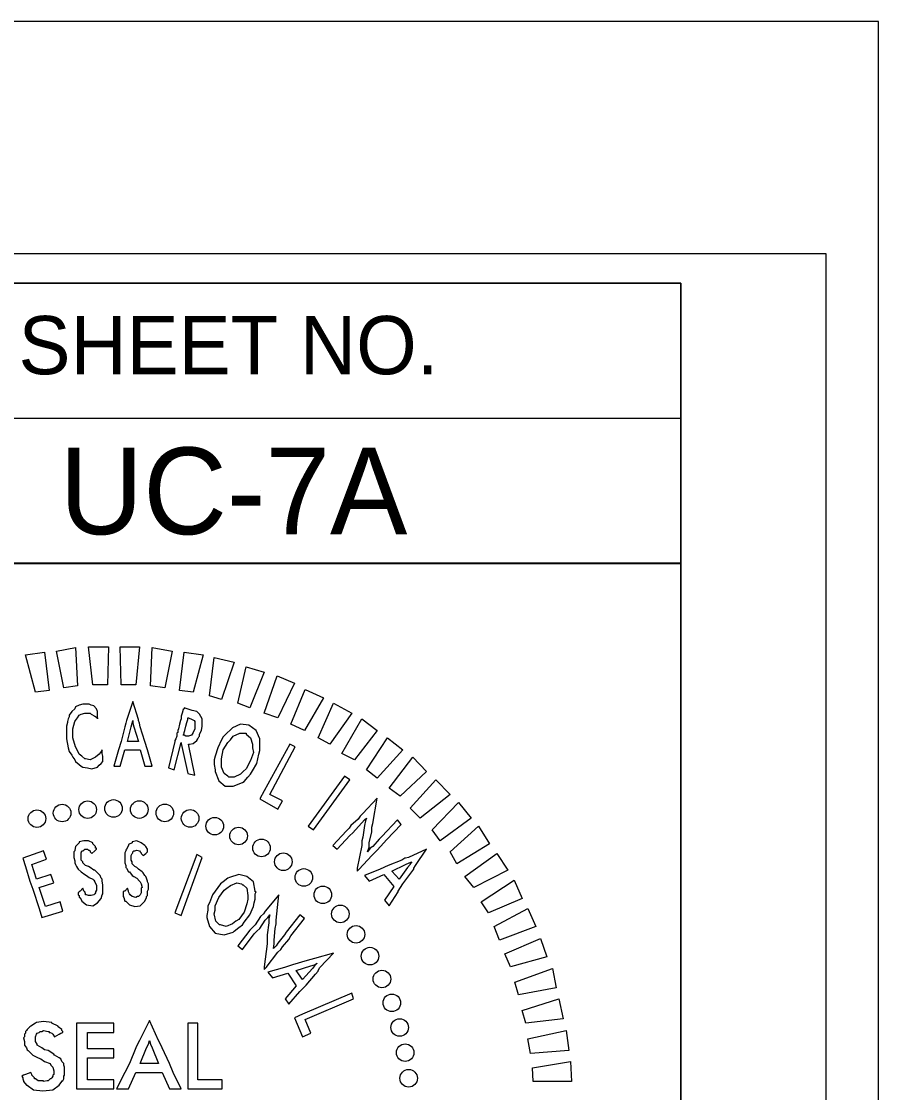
# Model space of a CAD drawing. Extents: x 0 to 4772457, y -312190 to 1506.
# Drawn here: x 2.7104 to 2.8333, y 1.6798 to 1.8333 of the extents above; entities that cross this region are included whole.
import ezdxf

# ---------------------------------------------------------------- set-up
doc = ezdxf.new("R2010")
doc.units = 0
for name, color, linetype in [('Legend CELL', 7, 'Continuous'), ('Old_Level_63', 7, 'Continuous'), ('Pullbox CELL', 7, 'Continuous')]:
    doc.layers.add(name, color=color, linetype=linetype)

msp = doc.modelspace()

# ---------------------------------------------------------------- linework, layer by layer
at = {"layer": 'Legend CELL'}
for p, q in [((2.4719, 1.77648), (2.80496, 1.77648)), ((2.74467, 1.76604), (2.74467, 1.76604))]:
    msp.add_line(p, q, dxfattribs=at)
for points in [[(2.4719, 1.79581), (2.80496, 1.79581), (2.80496, 1.75568)], [(2.80496, 1.75568), (2.4719, 1.75568), (2.4719, 1.79581)], [(2.80496, 1.56775), (2.63979, 1.56775), (2.63979, 1.7556), (2.80496, 1.7556)], [(2.80496, 1.7556), (2.80496, 1.56775)]]:
    msp.add_lwpolyline(points, dxfattribs=at)
at = {"layer": 'Old_Level_63'}
for points in [[(0.02749, 0.00833), (2.83333, 0.00833), (2.83333, 1.83333), (0.02749, 1.83333)], [(0.04916, 0.04166), (2.82583, 0.04166), (2.82583, 1.8), (0.04916, 1.8)], [(2.80499, 1.79583), (0.30499, 1.79583), (0.30499, 0.04583), (2.80499, 0.04583)]]:
    msp.add_lwpolyline(points, close=True, dxfattribs=at)
at = {"layer": 'Pullbox CELL'}
for points in [[(2.71245, 1.73716), (2.71101, 1.74252), (2.71376, 1.74291), (2.71441, 1.73742)], [(2.7165, 1.73781), (2.71545, 1.74304), (2.7182, 1.74357), (2.71846, 1.73808)], [(2.72068, 1.73821), (2.72003, 1.7437), (2.7229, 1.7437), (2.72277, 1.73821)], [(2.72473, 1.73821), (2.7246, 1.7437), (2.72735, 1.7437), (2.72683, 1.73821)], [(2.72892, 1.73808), (2.72918, 1.74357), (2.73205, 1.74304), (2.73101, 1.73781)], [(2.7331, 1.73742), (2.73375, 1.74291), (2.7365, 1.74252), (2.73506, 1.73716)], [(2.73741, 1.73664), (2.73807, 1.74213), (2.74094, 1.74147), (2.73911, 1.73612)], [(2.74147, 1.73559), (2.74264, 1.74082), (2.74526, 1.74004), (2.74317, 1.73494)], [(2.74526, 1.73415), (2.74709, 1.73951), (2.74957, 1.73847), (2.74722, 1.7335)], [(2.74905, 1.73259), (2.75114, 1.73755), (2.75375, 1.73638), (2.75101, 1.73167)], [(2.75297, 1.73063), (2.75519, 1.73559), (2.7578, 1.73415), (2.75467, 1.72971)], [(2.75637, 1.7284), (2.75924, 1.73337), (2.76146, 1.73167), (2.7582, 1.72749)], [(2.7599, 1.72605), (2.7629, 1.73063), (2.76512, 1.72893), (2.76146, 1.72487)], [(2.76316, 1.72344), (2.76656, 1.72788), (2.76852, 1.72579), (2.76473, 1.72226)], [(2.75676, 1.72514), (2.75153, 1.71795), (2.75231, 1.71742), (2.75754, 1.72461)], [(2.76617, 1.72056), (2.76983, 1.72461), (2.77192, 1.72252), (2.76761, 1.71912)], [(2.76931, 1.71742), (2.7731, 1.72135), (2.77493, 1.71912), (2.77048, 1.71586)], [(2.77192, 1.71429), (2.77597, 1.71795), (2.77754, 1.71546), (2.77284, 1.71259)], [(2.73558, 1.71389), (2.73245, 1.70553), (2.73336, 1.70514), (2.73637, 1.7135)], [(2.77401, 1.71076), (2.77859, 1.71403), (2.78016, 1.71167), (2.77532, 1.70919)], [(2.77637, 1.7071), (2.78107, 1.71023), (2.78225, 1.70762), (2.77741, 1.70553)], [(2.7782, 1.70357), (2.78303, 1.70618), (2.78421, 1.70357), (2.77898, 1.70161)], [(2.77976, 1.69965), (2.78486, 1.70187), (2.78578, 1.69926), (2.78055, 1.69782)], [(2.7812, 1.6956), (2.78656, 1.69756), (2.78708, 1.69481), (2.78172, 1.69377)], [(2.78225, 1.69154), (2.78748, 1.69324), (2.78813, 1.69037), (2.78277, 1.68971)], [(2.78303, 1.68749), (2.78852, 1.68867), (2.78891, 1.68579), (2.78342, 1.6854)], [(2.78369, 1.68331), (2.78918, 1.68422), (2.78931, 1.68135), (2.78382, 1.68135)]]:
    msp.add_lwpolyline(points, close=True, dxfattribs=at)
for points in [[(2.72134, 1.73442), (2.72121, 1.73481), (2.72081, 1.7352), (2.72042, 1.73533), (2.72016, 1.73546), (2.71925, 1.73546), (2.71872, 1.73533), (2.7182, 1.73507), (2.71807, 1.73481), (2.71768, 1.73442), (2.71728, 1.73389), (2.71728, 1.73376), (2.71728, 1.73363), (2.71715, 1.73337), (2.71702, 1.73298), (2.71702, 1.73285), (2.71689, 1.73232), (2.71689, 1.7318), (2.71689, 1.73049), (2.71715, 1.72919), (2.71728, 1.72866), (2.71768, 1.72814), (2.71781, 1.72788), (2.71807, 1.72749), (2.7182, 1.72723), (2.71872, 1.72683), (2.71898, 1.72657), (2.71925, 1.72644), (2.7199, 1.72631), (2.72055, 1.72618), (2.72134, 1.72644), (2.7216, 1.7267), (2.72186, 1.72697), (2.72212, 1.72723), (2.72212, 1.72775), (2.72212, 1.72801), (2.72199, 1.7284), (2.72199, 1.72866), (2.72199, 1.72893), (2.72186, 1.72866), (2.7216, 1.72827), (2.72108, 1.72788), (2.72029, 1.72749), (2.71964, 1.72762), (2.71951, 1.72762), (2.71911, 1.72801), (2.71872, 1.72827), (2.71846, 1.7288), (2.7182, 1.72932), (2.71781, 1.73063), (2.71781, 1.73193), (2.71794, 1.73246), (2.71807, 1.73298), (2.7182, 1.73311), (2.71846, 1.7335), (2.71872, 1.73389), (2.71898, 1.73402), (2.71951, 1.73415), (2.72029, 1.73415), (2.72042, 1.73402), (2.72094, 1.73376), (2.72134, 1.7335), (2.72134, 1.73337), (2.72134, 1.7335), (2.72134, 1.73389), (2.72134, 1.73415), (2.72134, 1.73429), (2.72134, 1.73442), (2.72134, 1.73442)], [(2.72722, 1.73311), (2.72722, 1.73324), (2.72643, 1.73585), (2.72552, 1.73311), (2.72539, 1.73272), (2.72526, 1.73219), (2.72473, 1.7301), (2.72434, 1.72893), (2.72369, 1.72657), (2.7246, 1.72657), (2.72526, 1.72893), (2.72748, 1.72893), (2.72813, 1.72657), (2.72918, 1.72657), (2.72853, 1.72893), (2.72813, 1.7301), (2.72748, 1.73219), (2.72735, 1.73272), (2.72722, 1.73311), (2.72722, 1.73311)], [(2.73637, 1.73298), (2.73637, 1.73337), (2.73598, 1.73402), (2.73558, 1.73442), (2.73493, 1.73455), (2.73375, 1.73494), (2.73375, 1.73481), (2.73362, 1.73468), (2.73349, 1.73415), (2.73336, 1.73376), (2.73336, 1.73363), (2.73336, 1.7335), (2.73336, 1.73337), (2.73323, 1.73311), (2.7331, 1.73259), (2.73297, 1.73193), (2.73284, 1.73167), (2.73284, 1.73141), (2.73271, 1.73128), (2.73271, 1.73089), (2.73258, 1.73049), (2.73245, 1.73023), (2.73245, 1.7301), (2.73153, 1.72631), (2.73232, 1.72605), (2.73336, 1.72997), (2.73336, 1.72984), (2.73428, 1.72553), (2.73532, 1.72527), (2.73441, 1.72971), (2.73454, 1.72971), (2.73506, 1.72984), (2.73558, 1.73023), (2.73571, 1.73049), (2.73585, 1.73076), (2.73598, 1.73089), (2.73598, 1.73115), (2.73624, 1.73167), (2.73637, 1.73232), (2.73637, 1.73259), (2.73637, 1.73272), (2.73637, 1.73298)], [(2.72643, 1.73311), (2.72643, 1.73272), (2.72656, 1.73219), (2.72722, 1.7301), (2.72565, 1.7301), (2.72617, 1.73219), (2.7263, 1.73272), (2.72643, 1.73311), (2.72643, 1.73311)], [(2.73441, 1.7335), (2.73493, 1.73324), (2.73519, 1.73311), (2.73532, 1.73298), (2.73532, 1.73259), (2.73532, 1.73193), (2.73506, 1.73141), (2.73493, 1.73115), (2.7348, 1.73102), (2.73441, 1.73089), (2.73402, 1.73089), (2.73375, 1.73102), (2.73362, 1.73102), (2.73375, 1.73128), (2.73375, 1.73141), (2.73388, 1.73167), (2.73402, 1.73232), (2.73415, 1.73285), (2.73428, 1.73324), (2.73428, 1.73337), (2.73428, 1.7335), (2.73441, 1.7335), (2.73441, 1.7335)], [(2.74186, 1.73259), (2.74068, 1.73206), (2.74055, 1.73193), (2.74042, 1.7318), (2.7399, 1.73128), (2.73937, 1.73076), (2.73911, 1.73036), (2.73859, 1.72919), (2.7382, 1.72801), (2.73807, 1.72749), (2.73807, 1.72683), (2.7382, 1.72605), (2.7382, 1.72579), (2.73872, 1.72448), (2.73964, 1.7237), (2.74081, 1.7237), (2.74212, 1.72422), (2.74238, 1.72435), (2.7429, 1.72501), (2.7433, 1.7254), (2.74356, 1.72592), (2.74421, 1.72697), (2.74447, 1.72827), (2.7446, 1.7288), (2.7446, 1.72932), (2.7446, 1.7301), (2.7446, 1.73036), (2.7446, 1.73049), (2.74408, 1.73167), (2.74303, 1.73246), (2.74186, 1.73259), (2.74186, 1.73259)], [(2.74264, 1.73128), (2.74264, 1.73115), (2.7433, 1.73063), (2.74356, 1.72971), (2.74356, 1.72919), (2.74369, 1.72853), (2.7433, 1.72736), (2.74264, 1.72618), (2.74225, 1.72579), (2.74186, 1.7254), (2.74094, 1.72501), (2.74029, 1.72501), (2.74016, 1.72501), (2.74003, 1.72514), (2.73951, 1.72553), (2.73911, 1.72644), (2.73911, 1.7271), (2.73911, 1.72762), (2.73937, 1.72893), (2.74003, 1.72997), (2.74042, 1.73036), (2.74081, 1.73089), (2.74173, 1.73128), (2.74251, 1.73128), (2.74264, 1.73128), (2.74264, 1.73128)], [(2.74526, 1.72304), (2.7446, 1.72187), (2.74722, 1.72043), (2.74787, 1.72161), (2.74604, 1.72252), (2.7497, 1.72932), (2.74892, 1.72971), (2.74526, 1.72304), (2.74526, 1.72304)], [(2.76003, 1.71429), (2.76029, 1.71494), (2.76029, 1.71559), (2.76068, 1.71716), (2.76068, 1.71782), (2.76081, 1.71834), (2.76146, 1.722), (2.75937, 1.71978), (2.75898, 1.71938), (2.75872, 1.71899), (2.75767, 1.71808), (2.75741, 1.71769), (2.75702, 1.71729), (2.75506, 1.7152), (2.75571, 1.71468), (2.75754, 1.71664), (2.75794, 1.71703), (2.75833, 1.71742), (2.75924, 1.71847), (2.75963, 1.71886), (2.7599, 1.71912), (2.75977, 1.71873), (2.75963, 1.71808), (2.75937, 1.71638), (2.75924, 1.71586), (2.75924, 1.7152), (2.75859, 1.71193), (2.75859, 1.71154), (2.75885, 1.7118), (2.76068, 1.71376), (2.76107, 1.71416), (2.76146, 1.71455), (2.76238, 1.71559), (2.76277, 1.71599), (2.76486, 1.71821), (2.76434, 1.71886), (2.76212, 1.71651), (2.76173, 1.71612), (2.76081, 1.71507), (2.76042, 1.71481), (2.76003, 1.71429), (2.76003, 1.71429)], [(2.71872, 1.71559), (2.71833, 1.7152), (2.7182, 1.71507), (2.71807, 1.71455), (2.71807, 1.71442), (2.71794, 1.71429), (2.71794, 1.71416), (2.71794, 1.71403), (2.71794, 1.71389), (2.71794, 1.71363), (2.71794, 1.7135), (2.71807, 1.71298), (2.71807, 1.71272), (2.7182, 1.71246), (2.71833, 1.7122), (2.71846, 1.71193), (2.71859, 1.7118), (2.71898, 1.71141), (2.71951, 1.71102), (2.71977, 1.71089), (2.72016, 1.71063), (2.72068, 1.71037), (2.72081, 1.71023), (2.72094, 1.70997), (2.72121, 1.70945), (2.72121, 1.70932), (2.72121, 1.70893), (2.72121, 1.7088), (2.72108, 1.70854), (2.72108, 1.7084), (2.72094, 1.70827), (2.72081, 1.70814), (2.72042, 1.70801), (2.72003, 1.70801), (2.71977, 1.70814), (2.71964, 1.70814), (2.71964, 1.70827), (2.71951, 1.70854), (2.71938, 1.70867), (2.71925, 1.70906), (2.71885, 1.70867), (2.71872, 1.70854), (2.71859, 1.7084), (2.71859, 1.70814), (2.71872, 1.70801), (2.71872, 1.70788), (2.71872, 1.70775), (2.71885, 1.70775), (2.71911, 1.70723), (2.71977, 1.70671), (2.72068, 1.70657), (2.72134, 1.70697), (2.72186, 1.70762), (2.72199, 1.70814), (2.72212, 1.70827), (2.72212, 1.70854), (2.72212, 1.70867), (2.72212, 1.70893), (2.72212, 1.70906), (2.72212, 1.70945), (2.72212, 1.70958), (2.72199, 1.7101), (2.72199, 1.71037), (2.72186, 1.7105), (2.72173, 1.71089), (2.72147, 1.71115), (2.72134, 1.71128), (2.72094, 1.71167), (2.72081, 1.71167), (2.72029, 1.71206), (2.72003, 1.7122), (2.71964, 1.71233), (2.71925, 1.71272), (2.71925, 1.71285), (2.71898, 1.71311), (2.71898, 1.71363), (2.71898, 1.71376), (2.71898, 1.71416), (2.71911, 1.71442), (2.71925, 1.71442), (2.71938, 1.71455), (2.71951, 1.71468), (2.7199, 1.71468), (2.72003, 1.71455), (2.72016, 1.71455), (2.72029, 1.71442), (2.72029, 1.71429), (2.72055, 1.71403), (2.72094, 1.71442), (2.72108, 1.71455), (2.72121, 1.71468), (2.72121, 1.71481), (2.72108, 1.71481), (2.72108, 1.71494), (2.72108, 1.71507), (2.72068, 1.71546), (2.72068, 1.71559), (2.72003, 1.71586), (2.71938, 1.71586), (2.71872, 1.71572), (2.71872, 1.71559), (2.71872, 1.71559)], [(2.7263, 1.71559), (2.72578, 1.71533), (2.72578, 1.7152), (2.72552, 1.71468), (2.72539, 1.71455), (2.72539, 1.71442), (2.72526, 1.71416), (2.72526, 1.71376), (2.72526, 1.71363), (2.72526, 1.71311), (2.72526, 1.71285), (2.72526, 1.71272), (2.72539, 1.71233), (2.72539, 1.71206), (2.72552, 1.71193), (2.72578, 1.71141), (2.72591, 1.71141), (2.7263, 1.71089), (2.72656, 1.71076), (2.72696, 1.7105), (2.72735, 1.7101), (2.72748, 1.70997), (2.72761, 1.70971), (2.72774, 1.70919), (2.72761, 1.70906), (2.72761, 1.70867), (2.72761, 1.70854), (2.72761, 1.7084), (2.72748, 1.70814), (2.72735, 1.70801), (2.72722, 1.70788), (2.72709, 1.70788), (2.72683, 1.70775), (2.7263, 1.70788), (2.72604, 1.70814), (2.72591, 1.70827), (2.72578, 1.70854), (2.72578, 1.70867), (2.72565, 1.70906), (2.72526, 1.70867), (2.72513, 1.70867), (2.725, 1.70854), (2.725, 1.70827), (2.725, 1.70814), (2.725, 1.70788), (2.72513, 1.70775), (2.72526, 1.70723), (2.72539, 1.70723), (2.72591, 1.70671), (2.7267, 1.70644), (2.72748, 1.70657), (2.72813, 1.70723), (2.72839, 1.70775), (2.72839, 1.70788), (2.72853, 1.70801), (2.72853, 1.70814), (2.72853, 1.7084), (2.72853, 1.70854), (2.72853, 1.70867), (2.72866, 1.70893), (2.72866, 1.70919), (2.72866, 1.70971), (2.72853, 1.70997), (2.72853, 1.7101), (2.72839, 1.7105), (2.72826, 1.71076), (2.72813, 1.71089), (2.72787, 1.71128), (2.72774, 1.71141), (2.72722, 1.7118), (2.72696, 1.71206), (2.7267, 1.7122), (2.7263, 1.71259), (2.7263, 1.71285), (2.72617, 1.71311), (2.72617, 1.71363), (2.72617, 1.71376), (2.7263, 1.71403), (2.72643, 1.71416), (2.72643, 1.71429), (2.72656, 1.71442), (2.7267, 1.71442), (2.72696, 1.71455), (2.72735, 1.71442), (2.72748, 1.71429), (2.72761, 1.71416), (2.72761, 1.71403), (2.72787, 1.71376), (2.72826, 1.71403), (2.72839, 1.71416), (2.72853, 1.71429), (2.72853, 1.71442), (2.72853, 1.71455), (2.72853, 1.71468), (2.72826, 1.71507), (2.72813, 1.7152), (2.72761, 1.71559), (2.72696, 1.71586), (2.7263, 1.71572), (2.7263, 1.71559), (2.7263, 1.71559)], [(2.71297, 1.70618), (2.71336, 1.70488), (2.71637, 1.70579), (2.71598, 1.7071), (2.71389, 1.70644), (2.71297, 1.70919), (2.71506, 1.70984), (2.71467, 1.71102), (2.71258, 1.71037), (2.71193, 1.71246), (2.71402, 1.71324), (2.71362, 1.71442), (2.71062, 1.71337), (2.71101, 1.7122), (2.71166, 1.7101), (2.71206, 1.70893), (2.71297, 1.70618), (2.71297, 1.70618)], [(2.76695, 1.71233), (2.76852, 1.71468), (2.76591, 1.7135), (2.76552, 1.71337), (2.76539, 1.71337), (2.76499, 1.71311), (2.76303, 1.71233), (2.76186, 1.7118), (2.75963, 1.71089), (2.76029, 1.7101), (2.76238, 1.71102), (2.76382, 1.70932), (2.76251, 1.70736), (2.76316, 1.70657), (2.76447, 1.70854), (2.76447, 1.70867), (2.76512, 1.70971), (2.76643, 1.71141), (2.76669, 1.7118), (2.76669, 1.71193), (2.76695, 1.71233), (2.76695, 1.71233)], [(2.76643, 1.71285), (2.76617, 1.71259), (2.76617, 1.71246), (2.76578, 1.71206), (2.7646, 1.71037), (2.76356, 1.71154), (2.76552, 1.71246), (2.76604, 1.71272), (2.76643, 1.71285), (2.76643, 1.71285)], [(2.7416, 1.71102), (2.74029, 1.71063), (2.74003, 1.7105), (2.73937, 1.70997), (2.73898, 1.70971), (2.73859, 1.70919), (2.73781, 1.70814), (2.73741, 1.70697), (2.73715, 1.70657), (2.73715, 1.70592), (2.73702, 1.70514), (2.73702, 1.70488), (2.73741, 1.70357), (2.7382, 1.70265), (2.73951, 1.70239), (2.74081, 1.70278), (2.74094, 1.70291), (2.7416, 1.70344), (2.74212, 1.70383), (2.74238, 1.70422), (2.74317, 1.70527), (2.74369, 1.70644), (2.74382, 1.70697), (2.74395, 1.70749), (2.74395, 1.70827), (2.74408, 1.70854), (2.74395, 1.70854), (2.74395, 1.70867), (2.74369, 1.70997), (2.74277, 1.71076), (2.7416, 1.71102), (2.7416, 1.71102)], [(2.74212, 1.70958), (2.74225, 1.70958), (2.74277, 1.70906), (2.7429, 1.70801), (2.7429, 1.70749), (2.74277, 1.70684), (2.74238, 1.70566), (2.7416, 1.70461), (2.7412, 1.70435), (2.74068, 1.70396), (2.73977, 1.70357), (2.73898, 1.70383), (2.73885, 1.70383), (2.73833, 1.70435), (2.73807, 1.7054), (2.7382, 1.70592), (2.7382, 1.70657), (2.73872, 1.70775), (2.73951, 1.7088), (2.7399, 1.70906), (2.74042, 1.70945), (2.74134, 1.70984), (2.74199, 1.70971), (2.74212, 1.70958), (2.74212, 1.70958)], [(2.74656, 1.70043), (2.74669, 1.70109), (2.74669, 1.70161), (2.74683, 1.70331), (2.74696, 1.70396), (2.74696, 1.70448), (2.74735, 1.70814), (2.74539, 1.70579), (2.74513, 1.7054), (2.74473, 1.70501), (2.74395, 1.70383), (2.74356, 1.70344), (2.74317, 1.70305), (2.74147, 1.70082), (2.74212, 1.7003), (2.74382, 1.70252), (2.74421, 1.70291), (2.7446, 1.70331), (2.74539, 1.70448), (2.74578, 1.70488), (2.74604, 1.70527), (2.74591, 1.70474), (2.74591, 1.70409), (2.74565, 1.70239), (2.74565, 1.70187), (2.74565, 1.70109), (2.74526, 1.69782), (2.74526, 1.69743), (2.74552, 1.69769), (2.74722, 1.69991), (2.74761, 1.7003), (2.74787, 1.70069), (2.74879, 1.70174), (2.74905, 1.70226), (2.75101, 1.70474), (2.75035, 1.70527), (2.74839, 1.70278), (2.74813, 1.70239), (2.74722, 1.70122), (2.74696, 1.70082), (2.74656, 1.70043), (2.74656, 1.70043)], [(2.75323, 1.69769), (2.75519, 1.69978), (2.75245, 1.69899), (2.75192, 1.69886), (2.7514, 1.69873), (2.74931, 1.69808), (2.74813, 1.69769), (2.74578, 1.69703), (2.74643, 1.69625), (2.74865, 1.6969), (2.74983, 1.69507), (2.74826, 1.69324), (2.74879, 1.69246), (2.75035, 1.69429), (2.75127, 1.6952), (2.75258, 1.69677), (2.75297, 1.69716), (2.75297, 1.69729), (2.75323, 1.69769), (2.75323, 1.69769)], [(2.75284, 1.69834), (2.75245, 1.69795), (2.75218, 1.69756), (2.75075, 1.69599), (2.74983, 1.69729), (2.75192, 1.69795), (2.75245, 1.69808), (2.75284, 1.69834), (2.75284, 1.69834)], [(2.75075, 1.69102), (2.74957, 1.6905), (2.75075, 1.68775), (2.75192, 1.68828), (2.75114, 1.69024), (2.75807, 1.69324), (2.7578, 1.69403), (2.75075, 1.69102), (2.75075, 1.69102)], [(2.71245, 1.68971), (2.71179, 1.68932), (2.71166, 1.68919), (2.71127, 1.6888), (2.71114, 1.68867), (2.71101, 1.68854), (2.71101, 1.68841), (2.71101, 1.68828), (2.71088, 1.68814), (2.71088, 1.68775), (2.71075, 1.68762), (2.71088, 1.6871), (2.71088, 1.68671), (2.71088, 1.68658), (2.71114, 1.68618), (2.71127, 1.68592), (2.7114, 1.68579), (2.71193, 1.68527), (2.71206, 1.68514), (2.71284, 1.68475), (2.71323, 1.68462), (2.71376, 1.68422), (2.71454, 1.68396), (2.71467, 1.6837), (2.71493, 1.68344), (2.71506, 1.68292), (2.71506, 1.68279), (2.71506, 1.68239), (2.71493, 1.68226), (2.71493, 1.68213), (2.7148, 1.68187), (2.71467, 1.68174), (2.71454, 1.68174), (2.71428, 1.68148), (2.71415, 1.68148), (2.71362, 1.68135), (2.71362, 1.68148), (2.71284, 1.68148), (2.71245, 1.68174), (2.71232, 1.68174), (2.71232, 1.68187), (2.71206, 1.68213), (2.71193, 1.68226), (2.71193, 1.68239), (2.71179, 1.68265), (2.71101, 1.68239), (2.71075, 1.68226), (2.71049, 1.68213), (2.71062, 1.68187), (2.71062, 1.68174), (2.71075, 1.68148), (2.71075, 1.68135), (2.71114, 1.68082), (2.71127, 1.68082), (2.71219, 1.68017), (2.71349, 1.68004), (2.71493, 1.68017), (2.71585, 1.68082), (2.71624, 1.68135), (2.71624, 1.68148), (2.71637, 1.68148), (2.7165, 1.68174), (2.7165, 1.68187), (2.7165, 1.68213), (2.71663, 1.68226), (2.71663, 1.68239), (2.71663, 1.68279), (2.71663, 1.68292), (2.71663, 1.68344), (2.7165, 1.6837), (2.7165, 1.68396), (2.71624, 1.68422), (2.71611, 1.68462), (2.71585, 1.68475), (2.71519, 1.68514), (2.71506, 1.68527), (2.71428, 1.68579), (2.71376, 1.68592), (2.71336, 1.68618), (2.71271, 1.68658), (2.71271, 1.68671), (2.71245, 1.6871), (2.71245, 1.68762), (2.71245, 1.68775), (2.71258, 1.68814), (2.71271, 1.68828), (2.71297, 1.68841), (2.7131, 1.68854), (2.71336, 1.68854), (2.71362, 1.68867), (2.71428, 1.68854), (2.71441, 1.68854), (2.71441, 1.68841), (2.71454, 1.68841), (2.7148, 1.68828), (2.71493, 1.68814), (2.71519, 1.68775), (2.71585, 1.68814), (2.71611, 1.68828), (2.71637, 1.68841), (2.71637, 1.68854), (2.71624, 1.68867), (2.71624, 1.6888), (2.71572, 1.68919), (2.71572, 1.68932), (2.7148, 1.68971), (2.7148, 1.68984), (2.71362, 1.68997), (2.71258, 1.68984), (2.71245, 1.68971), (2.71245, 1.68971)], [(2.71833, 1.68161), (2.71833, 1.6803), (2.72369, 1.6803), (2.72369, 1.68161), (2.7199, 1.68161), (2.7199, 1.68475), (2.72369, 1.68475), (2.72369, 1.68605), (2.7199, 1.68605), (2.7199, 1.68841), (2.72369, 1.68841), (2.72369, 1.68971), (2.71833, 1.68971), (2.71833, 1.68841), (2.71833, 1.68605), (2.71833, 1.68475), (2.71833, 1.68161), (2.71833, 1.68161)], [(2.73009, 1.68723), (2.72879, 1.69011), (2.72735, 1.68723), (2.72709, 1.68671), (2.72683, 1.68618), (2.72591, 1.68396), (2.72526, 1.68265), (2.72408, 1.6803), (2.72578, 1.6803), (2.72683, 1.68265), (2.73062, 1.68265), (2.73166, 1.6803), (2.73336, 1.6803), (2.73219, 1.68265), (2.73166, 1.68396), (2.73062, 1.68618), (2.73036, 1.68671), (2.73009, 1.68723), (2.73009, 1.68723)], [(2.73428, 1.68161), (2.73428, 1.6803), (2.73924, 1.6803), (2.73924, 1.68161), (2.73571, 1.68161), (2.73571, 1.68971), (2.73428, 1.68971), (2.73428, 1.68161), (2.73428, 1.68161)], [(2.72879, 1.68723), (2.72892, 1.68671), (2.72918, 1.68618), (2.73009, 1.68396), (2.72748, 1.68396), (2.72839, 1.68618), (2.72866, 1.68671), (2.72879, 1.68723), (2.72879, 1.68723)]]:
    msp.add_lwpolyline(points, dxfattribs=at)
for centre in [(2.71994, 1.72034), (2.72364, 1.72051), (2.72733, 1.72035), (2.71266, 1.71905), (2.71627, 1.71985), (2.731, 1.71987), (2.73462, 1.71908), (2.73815, 1.71797), (2.74157, 1.71656), (2.74486, 1.71485), (2.74798, 1.71287), (2.75092, 1.71062), (2.75365, 1.70812), (2.75616, 1.70539), (2.75841, 1.70246), (2.76041, 1.69934), (2.76212, 1.69606), (2.76354, 1.69264), (2.76466, 1.68911), (2.76546, 1.6855), (2.76595, 1.68183)]:
    msp.add_circle(centre, 0.00126, dxfattribs=at)

# ---------------------------------------------------------------- texts
at = {"layer": 'Legend CELL'}
msp.add_text('SHEET NO.', height=0.008352, dxfattribs=at).set_placement((2.71002, 1.78275))
at = {"layer": 'Old_Level_63'}
msp.add_text('UC-7A', height=0.01243, dxfattribs=at).set_placement((2.71589, 1.75982))

doc.saveas('drawing.dxf')
